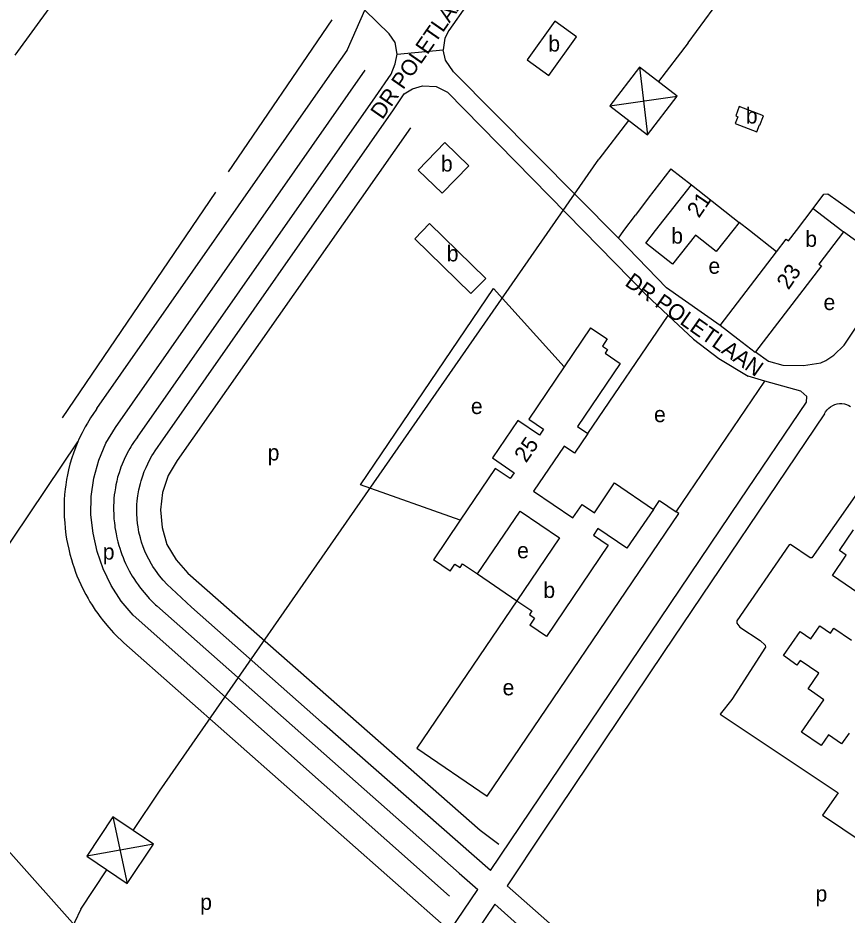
# Model space of a CAD drawing. Extents: x 158142 to 159655, y 385262 to 387204.
# Drawn here: x 159056.3 to 159265.7, y 385994 to 386220.3 of the extents above; entities that cross this region are included whole.
import ezdxf

# ---------------------------------------------------------------- set-up
doc = ezdxf.new("R2010")
doc.units = 0
for name, color, linetype in [('BLT_Basislijn', 7, 'Continuous'), ('BLT_Bebouwing', 7, 'Continuous'), ('BLT_Centroide', 7, 'Continuous'), ('BLT_Hoogspanningsmast_en_leidingen', 7, 'Continuous'), ('BLT_Huisnummer', 7, 'Continuous'), ('BLT_Straatnaam_verkleind', 7, 'Continuous'), ('BLT_Vlakafsluiter', 7, 'Continuous')]:
    doc.layers.add(name, color=color, linetype=linetype)

msp = doc.modelspace()

# ---------------------------------------------------------------- linework, layer by layer
at = {"layer": 'BLT_Basislijn'}
for p, q in [((159109.48, 386181.53), (159135.73, 386219.84)), ((159221.21, 386182.23), (159215.47, 386174.83)), ((159221.21, 386182.23), (159226.42, 386178.19)), ((159067.62, 386119.43), (159106.33, 386176.37)), ((159215.47, 386174.83), (159212.28, 386170.59)), ((159215.03, 386150.44), (159220.53, 386145.29)), ((159200.3, 386115.49), (159220.53, 386145.29)), ((159220.53, 386145.29), (159226.91, 386139.32)), ((159226.91, 386139.32), (159233.3, 386134.42)), ((159233.3, 386134.42), (159240.71, 386129.92)), ((159222.58, 386095.71), (159244.98, 386128.72)), ((159260, 386120.43), (159219.37, 386060.25)), ((159023.98, 386042.92), (159071.46, 386113.34)), ((159175.69, 386005.18), (159238.75, 386098.68)), ((159216.81, 386096.33), (159218.34, 386098.59)), ((159218.34, 386098.59), (159222.58, 386095.71)), ((159091.39, 386072.01), (159167.81, 386004.53)), ((159083.11, 386062.64), (159165.42, 385989.96)), ((159219.37, 386060.25), (159189.09, 386015.1)), ((159167.81, 386004.53), (159172.45, 386000.38)), ((159165.42, 385989.96), (159172.45, 386000.38)), ((159179.88, 386001.36), (159295.25, 385899.78)), ((159290.95, 385896.13), (159176.74, 385996.68))]:
    msp.add_line(p, q, dxfattribs=at)
for points in [[(159096.41, 386267.43), (159095.57, 386266.68), (159081.97, 386247.29), (159055.55, 386210.96)], [(159257.19, 386172.23), (159259.87, 386175.88), (159260.88, 386175.98), (159273.93, 386166.67), (159277.01, 386164.47), (159280.82, 386164.1), (159282.54, 386164.89), (159284.1, 386166.15), (159284.38, 386166.67), (159285.25, 386168.27), (159296.23, 386183.93), (159335.35, 386241.6)], [(159174.39, 386230.39), (159165.13, 386217.16), (159164.16, 386215.22), (159163.75, 386212.31)], [(159076.26, 386121.76), (159136.31, 386207.61), (159139.47, 386212.15), (159139.54, 386212.34), (159143.92, 386222.3)], [(159152.1, 386211.24), (159151.63, 386214.16), (159150.11, 386216.33), (159143.92, 386222.3)], [(159086.53, 386114.58), (159146.6, 386200.44), (159150.57, 386206.16), (159151.63, 386208.79), (159152.1, 386211.24)], [(159207.98, 386164.81), (159166.34, 386206.75), (159164.34, 386209.72), (159163.75, 386212.31)], [(159165.36, 385998.72), (159085.45, 386069.62), (159082.45, 386073.2), (159079.92, 386077.13), (159077.85, 386081.31), (159076.33, 386085.73), (159075.31, 386090.29), (159074.79, 386094.93), (159074.87, 386099.6), (159075.53, 386104.22), (159076.75, 386108.73), (159078.55, 386113.03), (159080.97, 386117.03), (159144.01, 386207.14)], [(159092.38, 386113.03), (159151.2, 386197.12), (159153.9, 386201.21), (159155.98, 386202.46), (159158.47, 386203.25)], [(159158.47, 386203.25), (159161.94, 386203.02), (159164.85, 386201.63), (159199.11, 386166.67), (159215.03, 386150.44)], [(159155.52, 386192.6), (159096.56, 386108.69), (159094.29, 386104.86), (159092.88, 386100.62), (159092.36, 386096.19), (159092.76, 386091.74), (159093.96, 386087.45), (159096.27, 386083.63), (159099.21, 386080.27), (159173.08, 386015.35), (159177.78, 386011.88)], [(159207.98, 386164.81), (159209.36, 386166.67), (159212.28, 386170.59)], [(159247.9, 386161.31), (159241.06, 386166.67), (159238.47, 386168.69)], [(159242.6, 386136.09), (159245.85, 386133.75), (159249.48, 386132.76), (159254.73, 386132.68), (159259.12, 386133.32), (159260.39, 386133.86), (159262.39, 386135.24), (159265.01, 386137.77), (159276.46, 386154.86), (159276.77, 386157.11), (159275.51, 386158.61), (159264.84, 386166.36)], [(159233.66, 386142.73), (159220.15, 386152.25), (159207.98, 386164.81)], [(159168.06, 386093.62), (159142.86, 386102.53), (159176.48, 386152.09), (159194.26, 386132.27)], [(159244.98, 386128.72), (159240.71, 386129.92)], [(159238.75, 386098.68), (159255.51, 386123.38), (159255.56, 386124.82), (159254.04, 386126.16), (159244.98, 386128.72)], [(159260, 386120.43), (159260.3, 386120.96), (159260.67, 386121.44), (159261.09, 386121.87), (159261.57, 386122.24), (159262.09, 386122.55), (159262.65, 386122.78), (159263.23, 386122.94), (159263.83, 386123.02), (159264.44, 386123.02), (159265.04, 386122.94), (159265.62, 386122.78), (159266.18, 386122.55), (159266.61, 386122.3)], [(159076.26, 386121.76), (159076.01, 386121.36), (159075.45, 386120.54), (159074.71, 386119.47), (159074.23, 386118.67), (159073.88, 386118.11), (159073.31, 386117.12), (159072.54, 386115.68), (159071.76, 386114.04), (159071.46, 386113.34)], [(159071.46, 386113.34), (159071.11, 386112.5), (159070.68, 386111.42), (159070.34, 386110.5), (159069.95, 386109.31), (159069.49, 386107.75), (159069.13, 386106.35), (159068.85, 386105.05), (159068.63, 386103.91), (159068.43, 386102.56), (159068.27, 386101.43), (159068.13, 386100.05), (159068.05, 386098.7), (159068.02, 386097.47), (159068, 386096.24), (159068.04, 386094.48), (159068.15, 386092.92), (159068.27, 386091.59), (159068.38, 386090.64), (159068.48, 386089.89), (159068.65, 386088.85), (159068.86, 386087.71), (159069.16, 386086.32), (159069.48, 386085.01), (159069.85, 386083.67), (159070.14, 386082.75), (159070.51, 386081.59), (159070.92, 386080.5), (159071.26, 386079.6), (159071.72, 386078.49), (159072.21, 386077.39), (159072.84, 386076.09), (159073.47, 386074.87), (159074.06, 386073.84), (159074.54, 386073.02), (159075.1, 386072.13), (159075.88, 386070.93), (159076.49, 386070.07), (159077.05, 386069.29), (159077.93, 386068.14), (159079.29, 386066.5), (159080.49, 386065.2), (159081.48, 386064.21), (159082.5, 386063.21), (159083.11, 386062.64)], [(159086.53, 386114.58), (159086.19, 386114.11), (159085.73, 386113.45), (159085.22, 386112.7), (159084.86, 386112.1), (159084.58, 386111.66), (159084.24, 386111.07), (159083.69, 386110.04), (159083.16, 386108.92), (159082.66, 386107.76), (159082.36, 386106.98), (159082.15, 386106.42), (159081.88, 386105.59), (159081.53, 386104.42), (159081.28, 386103.45), (159081.09, 386102.55), (159080.95, 386101.81), (159080.79, 386100.76), (159080.68, 386099.96), (159080.59, 386099.09), (159080.54, 386098.14), (159080.51, 386097.22), (159080.5, 386096.31), (159080.53, 386095.04), (159080.6, 386093.91), (159080.69, 386092.91), (159080.78, 386092.21), (159080.84, 386091.72), (159080.96, 386090.97), (159081.11, 386090.15), (159081.34, 386089.11), (159081.57, 386088.15), (159081.83, 386087.21), (159082.04, 386086.55), (159082.32, 386085.69), (159082.61, 386084.91), (159082.88, 386084.21), (159083.2, 386083.42), (159083.53, 386082.68), (159084.01, 386081.69), (159084.46, 386080.83), (159084.87, 386080.1), (159085.22, 386079.51), (159085.62, 386078.86), (159086.23, 386077.94), (159086.67, 386077.31), (159087.07, 386076.75), (159087.71, 386075.92), (159088.69, 386074.73), (159089.52, 386073.84), (159090.28, 386073.07), (159091.1, 386072.27), (159091.39, 386072.01)], [(159175.69, 386005.18), (159133.77, 386042), (159100.14, 386071.63), (159095.11, 386076.34), (159094.03, 386077.37), (159093.05, 386078.44), (159092.08, 386079.59), (159091.07, 386080.97), (159090.45, 386081.91), (159090.09, 386082.51), (159089.4, 386083.74), (159088.91, 386084.7), (159088.43, 386085.78), (159088, 386086.9), (159087.59, 386088.04), (159087.27, 386089.17), (159086.91, 386090.57), (159086.68, 386091.92), (159086.53, 386092.8), (159086.42, 386093.84), (159086.33, 386095.27), (159086.34, 386097.44), (159086.42, 386098.5), (159086.6, 386099.77), (159086.87, 386101.29), (159087.27, 386102.88), (159087.49, 386103.55), (159087.87, 386104.79), (159088.26, 386105.86), (159088.69, 386106.93), (159089.13, 386107.86), (159089.68, 386108.93), (159090.2, 386109.81), (159090.55, 386110.4), (159091.02, 386111.14), (159091.74, 386112.23), (159092.38, 386113.03)], [(159274.62, 386109.39), (159256.83, 386084.07), (159256.42, 386084.07), (159251.48, 386087.44), (159251.1, 386087.39), (159237.9, 386068.19), (159237.9, 386067.62), (159238.66, 386066.64), (159243.79, 386063.26), (159245.06, 386062.05), (159245.09, 386061.56), (159236.59, 386048.38)], [(159182.35, 386073.29), (159157.08, 386036.07), (159174.85, 386024), (159223.24, 386095.26), (159222.58, 386095.71)], [(159172.42, 386080.03), (159182.35, 386073.29)], [(159236.59, 386048.38), (159233.66, 386044.64), (159263.45, 386024.81), (159259.49, 386019.16), (159295.18, 385995.16)], [(159125.26, 385930.42), (159117.26, 385938.99), (159100, 385958.41), (159036.11, 386030.1), (159023.98, 386042.92)], [(159189.09, 386015.1), (159179.88, 386001.36)], [(159176.74, 385996.68), (159169.11, 385985.31)]]:
    msp.add_lwpolyline(points, dxfattribs=at)
at = {"layer": 'BLT_Bebouwing'}
msp.add_line((159226.42, 386178.19), (159238.47, 386168.69), dxfattribs=at)
for points in [[(159184.95, 386209.75), (159190.4, 386205.83), (159197.44, 386215.55), (159191.94, 386219.49)], [(159238.49, 386197.98), (159237.6, 386195.62), (159238.13, 386195.42), (159237.48, 386193.7), (159242.96, 386191.63), (159243.61, 386193.35), (159243.7, 386193.32), (159244.59, 386195.68)], [(159157.41, 386181.95), (159164.18, 386188.9), (159170.2, 386183.03), (159163.44, 386176.09)], [(159160.28, 386168.45), (159156.54, 386164.61), (159170.75, 386150.77), (159174.49, 386154.61)]]:
    msp.add_lwpolyline(points, close=True, dxfattribs=at)
for points in [[(159238.47, 386168.69), (159236.88, 386166.67), (159232.71, 386161.38), (159227.41, 386165.56), (159221.63, 386158.23), (159214.88, 386163.55), (159217.33, 386166.67), (159226.42, 386178.19)], [(159247.9, 386161.31), (159250.37, 386164.53), (159250.95, 386164.09), (159252.93, 386166.67), (159257.19, 386172.23)], [(159257.19, 386172.23), (159264.44, 386166.67), (159264.84, 386166.36)], [(159264.84, 386166.36), (159258.61, 386158.25), (159259.23, 386157.78), (159242.6, 386136.09)], [(159233.66, 386142.73), (159247.9, 386161.31)], [(159238.18, 386139.27), (159233.66, 386142.73)], [(159200.96, 386142.17), (159194.26, 386132.27)], [(159200.96, 386142.17), (159205.17, 386139.33)], [(159205.17, 386139.33), (159203.95, 386137.53), (159205.26, 386136.65), (159204.63, 386135.72), (159208.42, 386133.13), (159197.66, 386117.28), (159200.3, 386115.49)], [(159242.6, 386136.09), (159242.49, 386135.96), (159238.18, 386139.27)], [(159194.26, 386132.27), (159185.34, 386119.1), (159189.07, 386116.56), (159188.06, 386115.07), (159182.6, 386118.77), (159176.18, 386109.3), (159181.64, 386105.58), (159180.63, 386104.09), (159176.87, 386106.63), (159168.06, 386093.62)], [(159200.3, 386115.49), (159196.93, 386110.52), (159194.29, 386112.31), (159186.57, 386100.9), (159196.51, 386094.17), (159198.83, 386097.59), (159201.92, 386095.5), (159207.01, 386103), (159216.81, 386096.33)], [(159172.42, 386080.03), (159183.2, 386095.88), (159193.11, 386089.17), (159182.35, 386073.29)], [(159216.81, 386096.33), (159210.15, 386086.51)], [(159168.06, 386093.62), (159161.26, 386083.6)], [(159210.15, 386086.51), (159202.8, 386091.5), (159201.68, 386089.84), (159205.41, 386087.3)], [(159268.46, 386075.27), (159262.08, 386079.66), (159265.46, 386084.81), (159263.79, 386085.92), (159267.32, 386091.16)], [(159205.41, 386087.3), (159189.81, 386064.27), (159185.6, 386067.11)], [(159165.46, 386080.75), (159161.26, 386083.6)], [(159165.46, 386080.75), (159166.68, 386082.54), (159168, 386081.66), (159168.62, 386082.6), (159172.42, 386080.03)], [(159182.35, 386073.29), (159186.15, 386070.7), (159185.51, 386069.79), (159186.8, 386068.88), (159185.6, 386067.11)], [(159266.25, 386039.9), (159264.34, 386037.18), (159261.06, 386039.43), (159259.19, 386036.73), (159254.23, 386040.15), (159259.83, 386048.27), (159255.89, 386051.04), (159258.56, 386054.96), (159253.85, 386058.19), (159253, 386057.03), (159249.67, 386059.42), (159253.84, 386065.52), (159256.54, 386063.64), (159258.81, 386066.94), (159261.51, 386065.09), (159262.39, 386066.32), (159266.82, 386063.33)]]:
    msp.add_lwpolyline(points, dxfattribs=at)
at = {"layer": 'BLT_Hoogspanningsmast_en_leidingen'}
for p, q in [((159225.57, 386214.03), (159307.53, 386325.89)), ((159225.57, 386214.03), (159218.07, 386204.27)), ((159213.34, 386207.9), (159215.3, 386190.87)), ((159205.84, 386198.14), (159222.8, 386200.63)), ((159210.57, 386194.5), (159203.07, 386184.74)), ((159092.1, 386025.23), (159203.07, 386184.74)), ((159085.46, 386015.3), (159092.1, 386025.23)), ((159080.35, 386018.72), (159083.95, 386001.96)), ((159090.58, 386011.88), (159073.71, 386008.8)), ((159072.2, 385995.45), (159078.83, 386005.38)), ((159072.2, 385995.45), (159015.87, 385875.44))]:
    msp.add_line(p, q, dxfattribs=at)
for points in [[(159213.34, 386207.9), (159205.84, 386198.14), (159215.3, 386190.87), (159222.8, 386200.63)], [(159090.58, 386011.88), (159080.35, 386018.72), (159073.71, 386008.8), (159083.95, 386001.96)]]:
    msp.add_lwpolyline(points, close=True, dxfattribs=at)
at = {"layer": 'BLT_Vlakafsluiter'}
msp.add_line((159152.1, 386211.24), (159163.75, 386212.31), dxfattribs=at)

# ---------------------------------------------------------------- texts
at = {"layer": 'BLT_Centroide'}
for s, p in [('b', (159190.28, 386211.87)), ('b', (159240.16, 386193.7)), ('b', (159163.16, 386181.59)), ('b', (159221.32, 386163.39)), ('b', (159255.17, 386162.58)), ('b', (159164.63, 386158.91)), ('e', (159230.72, 386155.79)), ('e', (159259.78, 386146.63)), ('e', (159170.73, 386120.39)), ('e', (159216.97, 386118.34)), ('p', (159119.41, 386108.68)), ('p', (159077.77, 386083.65)), ('e', (159182.4, 386083.99)), ('b', (159189.03, 386073.98)), ('e', (159178.73, 386049.41)), ('p', (159257.76, 385997.37)), ('p', (159102.37, 385995.26))]:
    msp.add_text(s, height=4, dxfattribs=at).set_placement(p)
at = {"layer": 'BLT_Huisnummer'}
for s, p in [('21', (159228.31, 386169.67)), ('23', (159250.93, 386151.54)), ('25', (159184.68, 386107.89))]:
    msp.add_text(s, height=4, rotation=55.7112, dxfattribs=at).set_placement(p)
at = {"layer": 'BLT_Straatnaam_verkleind'}
for rotation, p in [(55.2331, (159148.37, 386194.51)), (325.007, (159209.38, 386153))]:
    msp.add_text('DR POLETLAAN', height=4, rotation=rotation, dxfattribs=at).set_placement(p)

doc.saveas('drawing.dxf')
